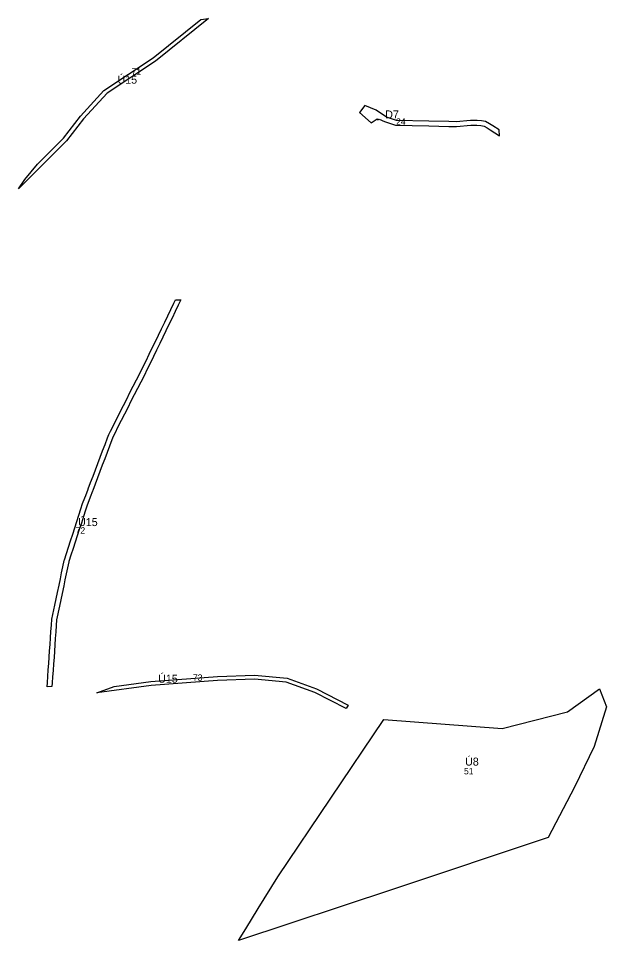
# Model space of a CAD drawing. Extents: x -521621 to -516857, y -1190025 to -1185894.
# Drawn here: x -517591 to -516857, y -1187258 to -1186107 of the extents above; entities that cross this region are included whole.
import ezdxf

# ---------------------------------------------------------------- set-up
doc = ezdxf.new("R2010")
doc.units = 0
for name, color, linetype in [('VPO_id', 7, 'Continuous'), ('VPO_n', 7, 'Continuous'), ('VPS_id', 7, 'Continuous'), ('VPS_n', 7, 'Continuous')]:
    doc.layers.add(name, color=color, linetype=linetype)

msp = doc.modelspace()

# ---------------------------------------------------------------- linework, layer by layer
at = {"layer": 'VPO_n'}
for points in [[(-517484.3, -1186196.9), (-517422.9, -1186156.3), (-517363.2, -1186108.3), (-517353.7, -1186107), (-517420, -1186160.3), (-517480.5, -1186200.3), (-517509.7, -1186232.4), (-517531, -1186259.8), (-517591.1, -1186319.7), (-517583.2, -1186308.3), (-517567.3, -1186288.9), (-517534.7, -1186256.5), (-517513.6, -1186229.1)], [(-517464, -1186598.3), (-517460, -1186590.3), (-517455.9, -1186582.3), (-517451.9, -1186574.3), (-517447.8, -1186566.3), (-517443.7, -1186558.3), (-517439.7, -1186550.3), (-517435.6, -1186542.4), (-517431.8, -1186534.4), (-517427.9, -1186526.4), (-517424, -1186518.4), (-517420.1, -1186510.4), (-517416.3, -1186502.4), (-517412.4, -1186494.4), (-517408.5, -1186486.4), (-517404.6, -1186478.4), (-517400.7, -1186470.4), (-517396.9, -1186462.4), (-517394.8, -1186458.2), (-517388.2, -1186458.3), (-517391.5, -1186465.1), (-517395.3, -1186473.1), (-517399.2, -1186481.1), (-517403.1, -1186489.1), (-517407, -1186497.1), (-517410.9, -1186505.1), (-517414.7, -1186513.1), (-517418.6, -1186521.1), (-517422.5, -1186529.1), (-517426.4, -1186537.1), (-517430.3, -1186545.1), (-517434.3, -1186553.1), (-517438.4, -1186561.1), (-517442.4, -1186569.1), (-517446.5, -1186577.1), (-517450.6, -1186585.1), (-517454.6, -1186593.1), (-517458.7, -1186601.1), (-517466.8, -1186617.1), (-517470.8, -1186625.1), (-517472.9, -1186629), (-517474.4, -1186633.1), (-517477.4, -1186641), (-517480.4, -1186648.9), (-517483.4, -1186656.9), (-517486.4, -1186664.8), (-517489.4, -1186672.8), (-517492.4, -1186680.7), (-517495.4, -1186688.6), (-517498.4, -1186696.6), (-517498.6, -1186697.1), (-517501.5, -1186705), (-517504.5, -1186712.9), (-517505.3, -1186714.9), (-517507.3, -1186721.1), (-517509.9, -1186729.1), (-517512.5, -1186737.1), (-517515.1, -1186745.1), (-517517.7, -1186753.1), (-517520.3, -1186761.1), (-517522.9, -1186769.1), (-517525.5, -1186777.1), (-517528, -1186785.1), (-517528.2, -1186785.5), (-517529.8, -1186793.1), (-517531.4, -1186800.6), (-517533, -1186808.2), (-517534.6, -1186815.7), (-517536.5, -1186825.1), (-517538.2, -1186833.1), (-517539.9, -1186841.1), (-517543.5, -1186858), (-517543.9, -1186865.1), (-517544.5, -1186873.1), (-517545.1, -1186881.1), (-517545.6, -1186889.1), (-517546.2, -1186897.1), (-517546.7, -1186905.1), (-517547.3, -1186913.1), (-517547.8, -1186921.1), (-517548.4, -1186929.1), (-517548.9, -1186936.7), (-517549.3, -1186941.3), (-517555.3, -1186941.8), (-517554.9, -1186936.3), (-517554.4, -1186928.6), (-517553.8, -1186920.6), (-517553.3, -1186912.6), (-517552.7, -1186904.6), (-517552.2, -1186896.6), (-517551.6, -1186888.6), (-517551, -1186880.6), (-517550.5, -1186872.6), (-517549.9, -1186864.6), (-517549.4, -1186857.2), (-517545.8, -1186839.8), (-517544.1, -1186831.8), (-517542.4, -1186823.8), (-517540.4, -1186814.5), (-517538.8, -1186806.9), (-517537.2, -1186799.4), (-517535.7, -1186791.8), (-517534, -1186784), (-517533.8, -1186783.2), (-517531.2, -1186775.2), (-517528.6, -1186767.2), (-517526, -1186759.2), (-517523.4, -1186751.2), (-517520.8, -1186743.2), (-517518.2, -1186735.2), (-517515.6, -1186727.2), (-517513, -1186719.2), (-517511, -1186712.9), (-517510.1, -1186710.8), (-517507.1, -1186702.8), (-517504.2, -1186694.9), (-517504, -1186694.5), (-517501, -1186686.5), (-517498, -1186678.6), (-517495, -1186670.6), (-517492, -1186662.7), (-517489, -1186654.8), (-517486, -1186646.8), (-517483, -1186638.9), (-517480, -1186630.9), (-517478.4, -1186626.6), (-517476.2, -1186622.3), (-517472.1, -1186614.4)], [(-517425.4, -1186940.1), (-517493.4, -1186949), (-517471.4, -1186941.1), (-517425.9, -1186935.1), (-517342.7, -1186928.8), (-517296.2, -1186927.2), (-517255.5, -1186930.9), (-517218.8, -1186944), (-517179.4, -1186964.6), (-517182, -1186968.8), (-517220.8, -1186948.6), (-517256.6, -1186935.9), (-517296.4, -1186932.2), (-517342.5, -1186933.7)], [(-517134.9, -1186982.4), (-516987, -1186993.8), (-516905.3, -1186972.8), (-516865.5, -1186944.2), (-516856.6, -1186966.5), (-516871.9, -1187016.2), (-516896.6, -1187066.8), (-516929.4, -1187129.9), (-517122.7, -1187194.2), (-517316.2, -1187258.5), (-517307.3, -1187244), (-517291.7, -1187218.6), (-517267.2, -1187178.8), (-517201.1, -1187080.6)]]:
    msp.add_lwpolyline(points, close=True, dxfattribs=at)
at = {"layer": 'VPS_n'}
msp.add_lwpolyline([(-517158.3, -1186215.8), (-517165.1, -1186224.3), (-517150.8, -1186237.4), (-517145.5, -1186234), (-517143, -1186232.4), (-517142.2, -1186233.7), (-517140.8, -1186232.9), (-517134.1, -1186235.8), (-517120, -1186240.3), (-517078.7, -1186241.2), (-517053.5, -1186241.8), (-517044, -1186242), (-517026.2, -1186240.3), (-517018.6, -1186240.3), (-517013.5, -1186240.7), (-517009.6, -1186241.5), (-517005.6, -1186243.6), (-517001.8, -1186246.1), (-516990.4, -1186253.6), (-516990.9, -1186246.1), (-516998.5, -1186241.1), (-517002.6, -1186238.4), (-517007.6, -1186235.8), (-517012.7, -1186234.7), (-517018.4, -1186234.3), (-517026.4, -1186234.3), (-517044.3, -1186236), (-517053.4, -1186235.8), (-517078.5, -1186235.2), (-517119, -1186234.4), (-517131.5, -1186230.4), (-517144.5, -1186221.5), (-517158.3, -1186215.8)], dxfattribs=at)

# ---------------------------------------------------------------- texts
at = {"layer": 'VPO_id'}
for s, p in [('71', (-517449.9, -1186177.4)), ('72', (-517519.7, -1186750.3)), ('73', (-517373.2, -1186934.1)), ('51', (-517034.7, -1187051))]:
    msp.add_text(s, height=8, dxfattribs=at).set_placement(p)
at = {"layer": 'VPO_n'}
for s, p in [('Ú15', (-517467.5, -1186188.5)), ('Ú15', (-517516.7, -1186740.9)), ('Ú15', (-517416.7, -1186936.5)), ('Ú8', (-517033.3, -1187040))]:
    msp.add_text(s, height=10, dxfattribs=at).set_placement(p)
at = {"layer": 'VPS_id'}
msp.add_text('24', height=8, dxfattribs=at).set_placement((-517119.5, -1186239.8))
at = {"layer": 'VPS_n'}
msp.add_text('D7', height=10, dxfattribs=at).set_placement((-517133.1, -1186231.9))

doc.saveas('drawing.dxf')
